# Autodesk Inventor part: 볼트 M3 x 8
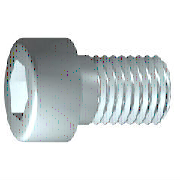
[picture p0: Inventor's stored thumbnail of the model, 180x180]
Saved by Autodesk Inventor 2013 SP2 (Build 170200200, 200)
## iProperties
IsCustomPart: 0
Created: 2012-02
Part Number: 볼트 M3 x 8
Material: 스테인리스강
Description: 6각 소켓 머리 캡 나사
Document SubType Name: Modeling
Standard: ISO 4762
Designer: mduedu
Standard Revision: Fourth edition 2004-03-01
Standards Organization: ISO
Language: ko-KR
Size Designation: M3 x 8
Categories: <MemberInstance><Categories><Category DisplayName="조임쇠" InternalName="e4da775c-781d-43d5-af7c-5136215cf5a6" Mnemonic="FSTN"><Category DisplayName="볼트" InternalN
Density: 8.08 g/cm^3
Author: mduedu
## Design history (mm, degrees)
sketch "스케치1"
  geometry: L1 (-0.867, 0)-(8, 0); L2 (8, 0)-(8, 1.5); L3 (8, 1.5)-(1.25, 1.5); L4 (1.25, 1.5)-(0.943, 1.5); L5 (0.943, 1.5)-(0, 1.5); L6 (0, 1.5)-(0, 2.75); L7 (0, 2.75)-(-3, 2.75); L8 (-3, 2.75)-(-3, 1.443); L9 (-3, 1.443)-(-1.7, 1.443); L10 (-1.7, 1.443)-(-0.867, 0); L11 (-5.2, 0)-(10.2, 0) reference; L12 (0, -0.55)-(0, 3.3) reference; L13 (1.25, 1.5)-(0, 1.5)
  constraints: 22 end point, 6 parallel, 2 collinear, 2 perpendicular, 1 horizontal, 1 point on line
  dimensions: "d1" = 6.75 distance from line of L3.end L2 (= GEL); "d2" = 0.30683 distance of L4.end L3.end (computed from GAL); "d3" = 3 distance between parallel lines of L8 L6 (= KOH); "d4" = 1.3 distance of L8.end L9.end (= INTI); "d5" = 60 deg angle of L10 L1; "d6" = 3 diameter of L3 L1 (= GD); "d7" = 3 diameter of L5 L1 (= BDM); "d8" = 2.88675 diameter of L9 L1 (= 1.1547 x SW); "d9" = 5.5 diameter of L7 L1 (= KOD); "d26" = 8 distance between parallel lines of L12 L2 (= NLG)
revolve "본체" sketch "스케치1" stored, may be unused: angle "d10" = 90 deg
sketch "스케치2"
  geometry: L1 (0, -3.85)-(0, 3.85) reference; L2 (-3.85, 0)-(3.85, 0) reference; L3 (1.443, 0)-(0.722, -1.25); L4 (0.722, -1.25)-(-0.722, -1.25); L5 (-0.722, -1.25)-(-1.443, 0); L6 (-1.443, 0)-(-0.722, 1.25); L7 (-0.722, 1.25)-(0.722, 1.25); L8 (0.722, 1.25)-(1.443, 0); 2 further points
  constraints: 12 end point, 1 coincident, 1 horizontal alignment, 1 point on line, 12 other
extrude "슬롯" join sketch "스케치2" stored distance "d11" = 10; taper "d12" = 0 deg
workplane "Work Plane1"
fillet "Fillet2" dims "d30" = 0.1 (= R)
body "Solid1"
fillet "모깎기1" dims "d17" = 0.3 (= RR)
feature "스레드" dims "d13" = 6.75 (= GEL), "d14" = 0
chamfer "모따기1" distance "d15" = 0.30673 (= -0.5 x SPD + 0.5 x GD); stored, may be unused: second distance "d16" = 0.30673 (= GUL), angle "d27" = 45 deg
other parameters: "GD" = 3 [user parameter; used in 2 equation terms], "NLG" = 8 [user parameter; used in 1 equation term], "GEL" = 6.75 [user parameter; used in 2 equation terms], "KOD" = 5.5 [user parameter; used in 1 equation term], "KOH" = 3 [user parameter; used in 1 equation term], "INTI" = 1.3 [user parameter; used in 1 equation term], "GAL" = 0.30673 (= 0.61345 x PTC) [user parameter; used in 1 equation term], "GUL" = 0.30673 (= 0.61345 x PTC) [user parameter; used in 1 equation term], "BDM" = 3 (= NND) [user parameter; used in 1 equation term], "SW" = 2.5 [user parameter; used in 2 equation terms], "RR" = 0.3 [user parameter; used in 1 equation term], "SPD" = 2.38655 (= NND - 1.2269 x PTC) [user parameter; used in 1 equation term], "d19" = 0, "d28" = 0, "d29" = 0, "R" = 0.1 [user parameter; used in 1 equation term], "TOA" = 30 deg [user parameter], "GD1" = 2.38655 (= THREADDIA - 1.2269 x PTC) [user parameter], "THREADDIA" = 3 [user parameter; used in 1 equation term], "FAWI" = 45 deg [user parameter], "PTC" = 0.5 [user parameter; used in 5 equation terms], "NND" = 3 [user parameter; used in 2 equation terms], "E0" = 2.8875 (= 1.155 x SW) [user parameter]
